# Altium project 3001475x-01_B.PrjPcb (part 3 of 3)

## Sheet 11 - Expansion Connectors, User LEDs.SchDoc: Expansion connectors, User LEDs
size A3; PageSetup: Record=PageOptions|CenterHorizontal=True|CenterVertical=True|PrintScale=0.70|XCorrection=1.00|YCorrection=1.00|PrintKind=0|BorderSize=5000000|LeftOffset=0|BottomOffset=0|Orientation=2|PaperLength=4200|PaperWidth=2970|Scale=100|PaperSource=7|PrintQuality=600|MediaType=1|DitherType=10|PaperKind=A4|PrintScaleMode=1; Author: Daniel Alesanco; SheetNumber: 11; SheetTotal: 13
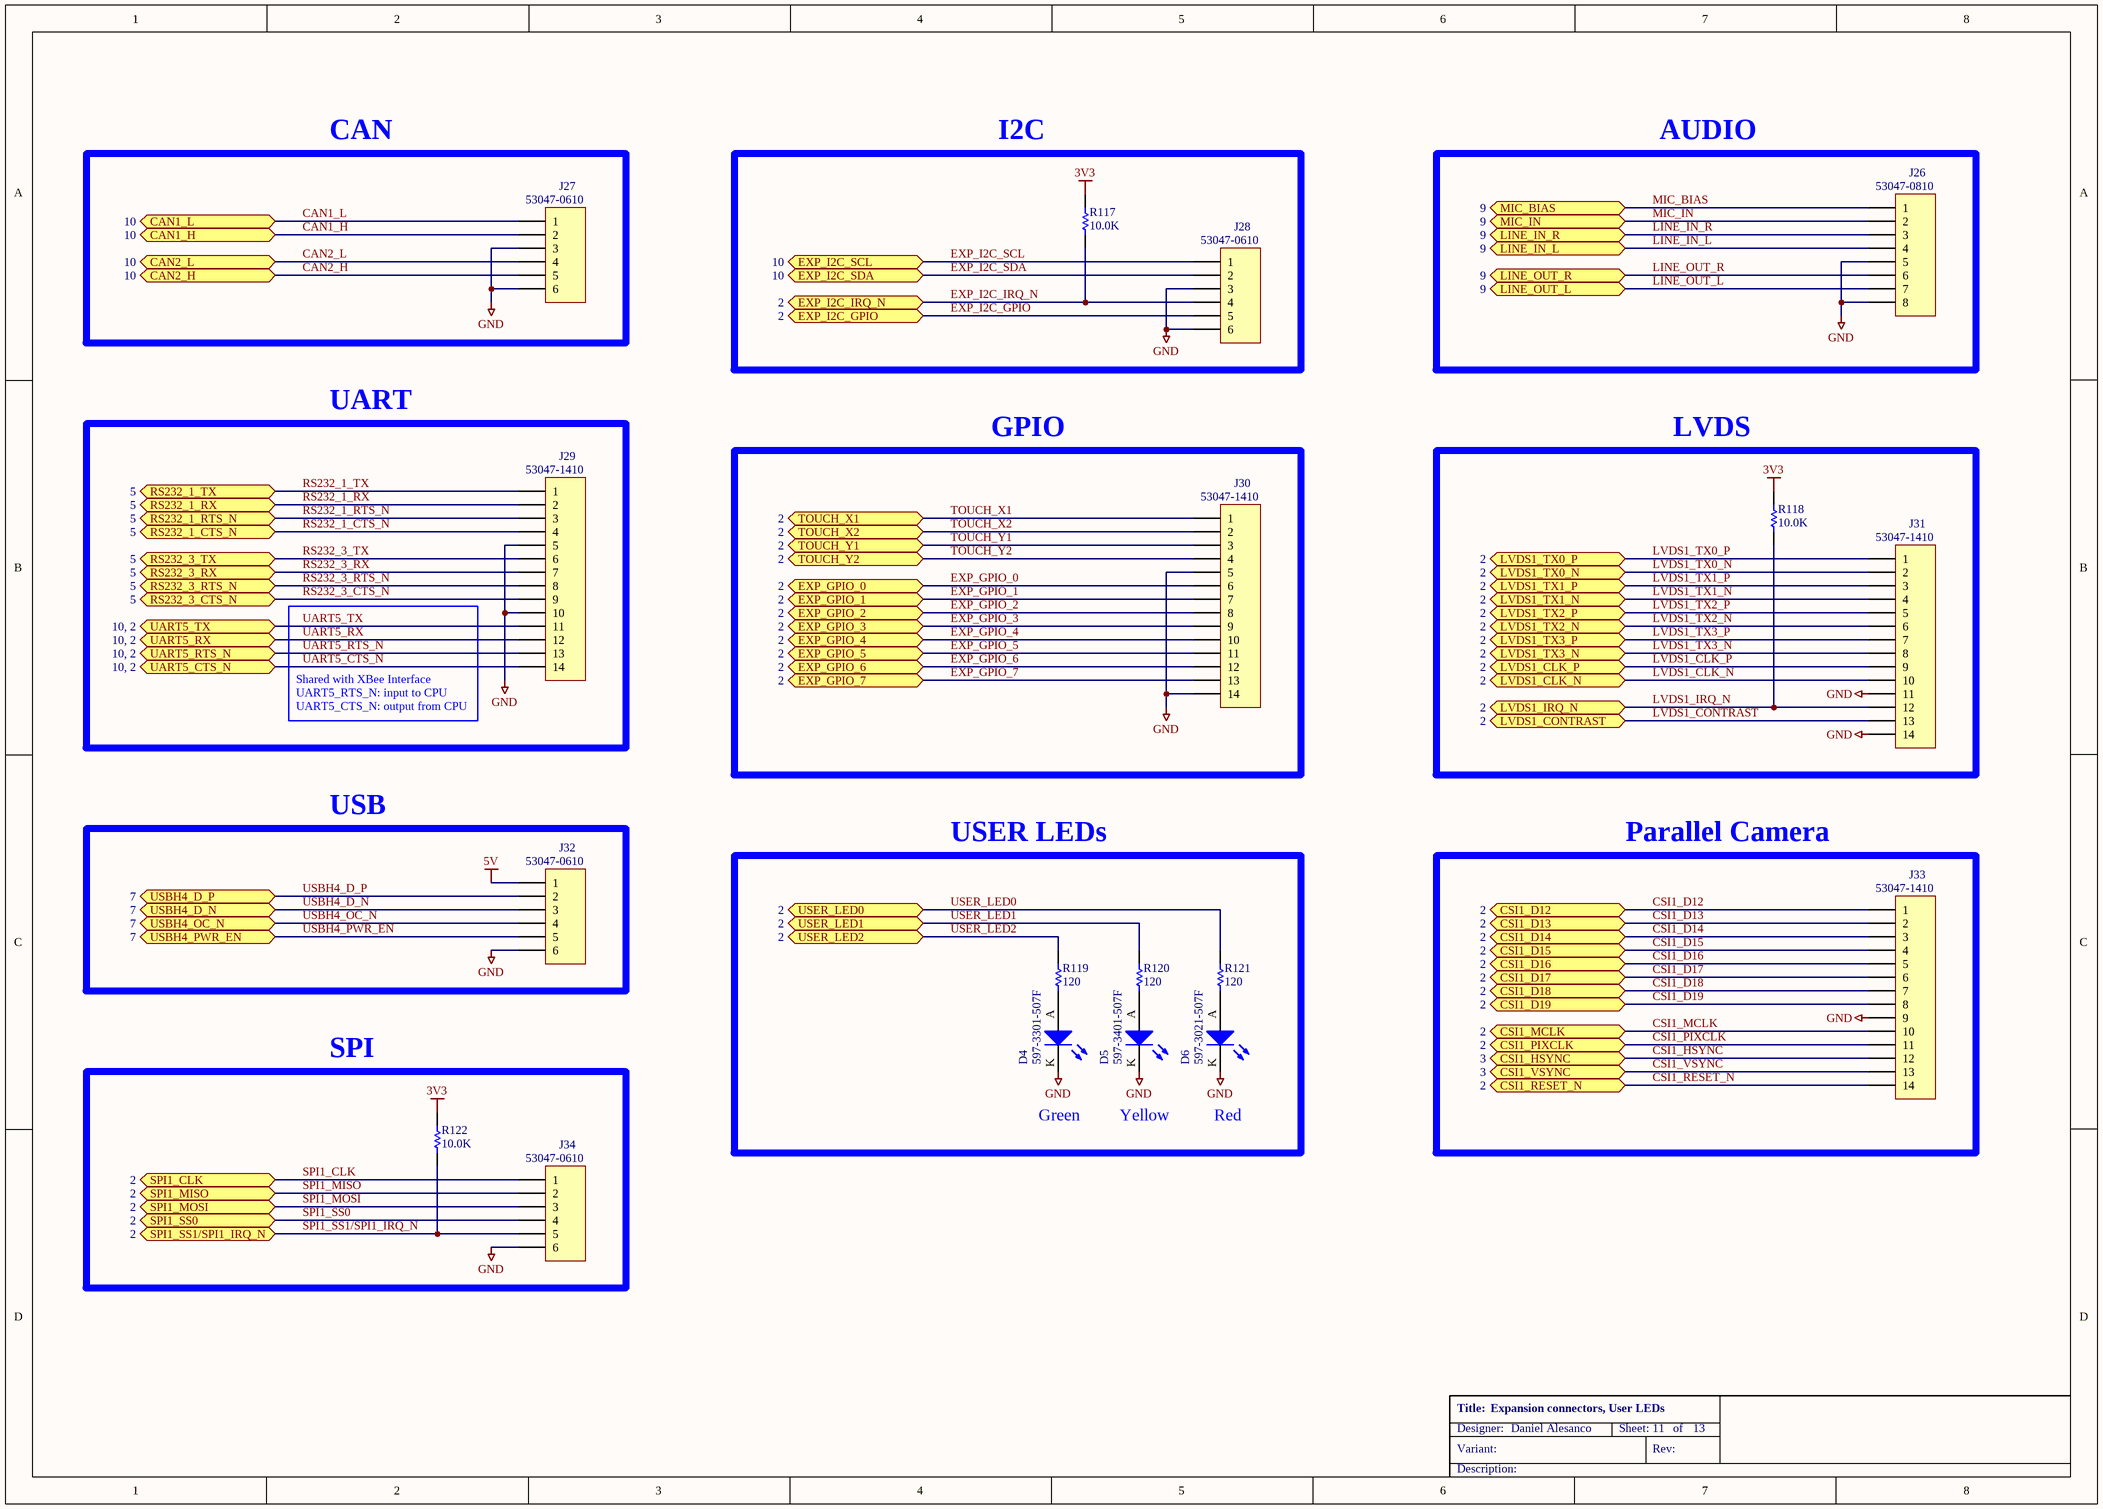
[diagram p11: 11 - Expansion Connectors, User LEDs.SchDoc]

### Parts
D4  597-3301-507F  [LEDM3020X130N]
D5  597-3401-507F  [LEDM3020X130N]
D6  597-3021-507F  [LEDM3020X130N]
J26  Manufacturer_Part_Number: 53047-0810  [MOLEX_53047-0810]  (hidden comment: 1x8P)
J27  Manufacturer_Part_Number: 53047-0610  [MOLEX_53047-0610]  (hidden comment: 1x6P)
J28  Manufacturer_Part_Number: 53047-0610  [MOLEX_53047-0610]  (hidden comment: 1x6P)
J29  Manufacturer_Part_Number: 53047-1410  [MOLEX_53047-1410]  (hidden comment: 1x14P)
J30  Manufacturer_Part_Number: 53047-1410  [MOLEX_53047-1410]  (hidden comment: 1x14P)
J31  Manufacturer_Part_Number: 53047-1410  [MOLEX_53047-1410]  (hidden comment: 1x14P)
J32  Manufacturer_Part_Number: 53047-0610  [MOLEX_53047-0610]  (hidden comment: 1x6P)
J33  Manufacturer_Part_Number: 53047-1410  [MOLEX_53047-1410]  (hidden comment: 1x14P)
J34  Manufacturer_Part_Number: 53047-0610  [MOLEX_53047-0610]  (hidden comment: 1x6P)
R117  10.0K  [RESC1005X40N]
R118  10.0K  [RESC1005X40N]
R119  120  [RESC1005X40N]
R120  120  [RESC1005X40N]
R121  120  [RESC1005X40N]
R122  10.0K  [RESC1005X40N]

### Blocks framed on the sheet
CAN: J27
I2C: J28 R117
AUDIO: J26
UART: J29
GPIO: J30
LVDS: J31 R118
USB: J32
USER LEDs: D4-D6 R119-R121
Parallel Camera: J33
SPI: J34 R122

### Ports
CAN1_H (bidir, see 10), CAN1_L (bidir, see 10), CAN2_H (bidir, see 10), CAN2_L (bidir, see 10), CSI1_D12 (bidir, see 2), CSI1_D13 (bidir, see 2), CSI1_D14 (bidir, see 2), CSI1_D15 (bidir, see 2), CSI1_D16 (bidir, see 2), CSI1_D17 (bidir, see 2), CSI1_D18 (bidir, see 2), CSI1_D19 (bidir, see 2), CSI1_HSYNC (bidir, see 3), CSI1_MCLK (bidir, see 2), CSI1_PIXCLK (bidir, see 2), CSI1_RESET_N (bidir, see 2), CSI1_VSYNC (bidir, see 3), EXP_GPIO_0 (bidir, see 2), EXP_GPIO_1 (bidir, see 2), EXP_GPIO_2 (bidir, see 2), EXP_GPIO_3 (bidir, see 2), EXP_GPIO_4 (bidir, see 2), EXP_GPIO_5 (bidir, see 2), EXP_GPIO_6 (bidir, see 2), EXP_GPIO_7 (bidir, see 2), EXP_I2C_GPIO (bidir, see 2), EXP_I2C_IRQ_N (bidir, see 2), EXP_I2C_SCL (bidir, see 10), EXP_I2C_SDA (bidir, see 10), LINE_IN_L (bidir, see 9), LINE_IN_R (bidir, see 9), LINE_OUT_L (bidir, see 9), LINE_OUT_R (bidir, see 9), LVDS1_CLK_N (bidir, see 2), LVDS1_CLK_P (bidir, see 2), LVDS1_CONTRAST (bidir, see 2), LVDS1_IRQ_N (bidir, see 2), LVDS1_TX0_N (bidir, see 2), LVDS1_TX0_P (bidir, see 2), LVDS1_TX1_N (bidir, see 2), LVDS1_TX1_P (bidir, see 2), LVDS1_TX2_N (bidir, see 2), LVDS1_TX2_P (bidir, see 2), LVDS1_TX3_N (bidir, see 2), LVDS1_TX3_P (bidir, see 2), MIC_BIAS (bidir, see 9), MIC_IN (bidir, see 9), RS232_1_CTS_N (bidir, see 5), RS232_1_RTS_N (bidir, see 5), RS232_1_RX (bidir, see 5), RS232_1_TX (bidir, see 5), RS232_3_CTS_N (bidir, see 5), RS232_3_RTS_N (bidir, see 5), RS232_3_RX (bidir, see 5), RS232_3_TX (bidir, see 5), SPI1_CLK (bidir, see 2), SPI1_MISO (bidir, see 2), SPI1_MOSI (bidir, see 2), SPI1_SS0 (bidir, see 2), SPI1_SS1/SPI1_IRQ_N (bidir, see 2), TOUCH_X1 (bidir, see 2), TOUCH_X2 (bidir, see 2), TOUCH_Y1 (bidir, see 2), TOUCH_Y2 (bidir, see 2), UART5_CTS_N (bidir, see 10, 2), UART5_RTS_N (bidir, see 10, 2), UART5_RX (bidir, see 10, 2), UART5_TX (bidir, see 10, 2), USBH4_D_N (bidir, see 7), USBH4_D_P (bidir, see 7), USBH4_OC_N (bidir, see 7), USBH4_PWR_EN (bidir, see 7), USER_LED0 (bidir, see 2), USER_LED1 (bidir, see 2), USER_LED2 (bidir, see 2)

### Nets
3V3: R117.1 R118.1 R122.1
5V: J32.1
GND: D4.K D5.K D6.K J26.5 J26.8 J27.3 J27.6 J28.3 J28.6 J29.5 J29.10 J30.5 J30.14 J31.11 J31.14 J32.6 J33.9 J34.6
CAN1_H: J27.2 ; port CAN1_H
CAN1_L: J27.1 ; port CAN1_L
CAN2_H: J27.5 ; port CAN2_H
CAN2_L: J27.4 ; port CAN2_L
CSI1_D12: J33.1 ; port CSI1_D12
CSI1_D13: J33.2 ; port CSI1_D13
CSI1_D14: J33.3 ; port CSI1_D14
CSI1_D15: J33.4 ; port CSI1_D15
CSI1_D16: J33.5 ; port CSI1_D16
CSI1_D17: J33.6 ; port CSI1_D17
CSI1_D18: J33.7 ; port CSI1_D18
CSI1_D19: J33.8 ; port CSI1_D19
CSI1_HSYNC: J33.12 ; port CSI1_HSYNC
CSI1_MCLK: J33.10 ; port CSI1_MCLK
CSI1_PIXCLK: J33.11 ; port CSI1_PIXCLK
CSI1_RESET_N: J33.14 ; port CSI1_RESET_N
CSI1_VSYNC: J33.13 ; port CSI1_VSYNC
EXP_GPIO_0: J30.6 ; port EXP_GPIO_0
EXP_GPIO_1: J30.7 ; port EXP_GPIO_1
EXP_GPIO_2: J30.8 ; port EXP_GPIO_2
EXP_GPIO_3: J30.9 ; port EXP_GPIO_3
EXP_GPIO_4: J30.10 ; port EXP_GPIO_4
EXP_GPIO_5: J30.11 ; port EXP_GPIO_5
EXP_GPIO_6: J30.12 ; port EXP_GPIO_6
EXP_GPIO_7: J30.13 ; port EXP_GPIO_7
EXP_I2C_GPIO: J28.5 ; port EXP_I2C_GPIO
EXP_I2C_IRQ_N: J28.4 R117.2 ; port EXP_I2C_IRQ_N
EXP_I2C_SCL: J28.1 ; port EXP_I2C_SCL
EXP_I2C_SDA: J28.2 ; port EXP_I2C_SDA
LINE_IN_L: J26.4 ; port LINE_IN_L
LINE_IN_R: J26.3 ; port LINE_IN_R
LINE_OUT_L: J26.7 ; port LINE_OUT_L
LINE_OUT_R: J26.6 ; port LINE_OUT_R
LVDS1_CLK_N: J31.10 ; port LVDS1_CLK_N
LVDS1_CLK_P: J31.9 ; port LVDS1_CLK_P
LVDS1_CONTRAST: J31.13 ; port LVDS1_CONTRAST
LVDS1_IRQ_N: J31.12 R118.2 ; port LVDS1_IRQ_N
LVDS1_TX0_N: J31.2 ; port LVDS1_TX0_N
LVDS1_TX0_P: J31.1 ; port LVDS1_TX0_P
LVDS1_TX1_N: J31.4 ; port LVDS1_TX1_N
LVDS1_TX1_P: J31.3 ; port LVDS1_TX1_P
LVDS1_TX2_N: J31.6 ; port LVDS1_TX2_N
LVDS1_TX2_P: J31.5 ; port LVDS1_TX2_P
LVDS1_TX3_N: J31.8 ; port LVDS1_TX3_N
LVDS1_TX3_P: J31.7 ; port LVDS1_TX3_P
MIC_BIAS: J26.1 ; port MIC_BIAS
MIC_IN: J26.2 ; port MIC_IN
RS232_1_CTS_N: J29.4 ; port RS232_1_CTS_N
RS232_1_RTS_N: J29.3 ; port RS232_1_RTS_N
RS232_1_RX: J29.2 ; port RS232_1_RX
RS232_1_TX: J29.1 ; port RS232_1_TX
RS232_3_CTS_N: J29.9 ; port RS232_3_CTS_N
RS232_3_RTS_N: J29.8 ; port RS232_3_RTS_N
RS232_3_RX: J29.7 ; port RS232_3_RX
RS232_3_TX: J29.6 ; port RS232_3_TX
SPI1_CLK: J34.1 ; port SPI1_CLK
SPI1_MISO: J34.2 ; port SPI1_MISO
SPI1_MOSI: J34.3 ; port SPI1_MOSI
SPI1_SS0: J34.4 ; port SPI1_SS0
SPI1_SS1/SPI1_IRQ_N: J34.5 R122.2 ; port SPI1_SS1/SPI1_IRQ_N
TOUCH_X1: J30.1 ; port TOUCH_X1
TOUCH_X2: J30.2 ; port TOUCH_X2
TOUCH_Y1: J30.3 ; port TOUCH_Y1
TOUCH_Y2: J30.4 ; port TOUCH_Y2
UART5_CTS_N: J29.14 ; port UART5_CTS_N
UART5_RTS_N: J29.13 ; port UART5_RTS_N
UART5_RX: J29.12 ; port UART5_RX
UART5_TX: J29.11 ; port UART5_TX
USBH4_D_N: J32.3 ; port USBH4_D_N
USBH4_D_P: J32.2 ; port USBH4_D_P
USBH4_OC_N: J32.4 ; port USBH4_OC_N
USBH4_PWR_EN: J32.5 ; port USBH4_PWR_EN
USER_LED0: R121.2 ; port USER_LED0
USER_LED1: R120.2 ; port USER_LED1
USER_LED2: R119.2 ; port USER_LED2
NetD4_A: D4.A R119.1
NetD5_A: D5.A R120.1
NetD6_A: D6.A R121.1

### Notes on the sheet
- Shared with XBee Interface
- UART5_RTS_N: input to CPU
- UART5_CTS_N: output from CPU
- Green
- Yellow
- Red

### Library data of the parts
D4 = 1001189: LED GREEN 573NM 1208 SMD; Manufacturer: Dialight; Digi_PN: 17050183; Component_Life_Cycle_State: Reviewed; Area: 6; Project: CCWMX6_SBC board
D5 = 1001188: LED YELLOW 588NM 1208 SMD; Manufacturer: Dialight; Digi_PN: 17050387; Component_Life_Cycle_State: Reviewed; Area: 6; Project: CCWMX6_SBC board
D6 = 1001190: LED RED 653NM 20MA 1208 SMD; Manufacturer: Dialight; Digi_PN: 17050184; Component_Life_Cycle_State: Reviewed; Area: 6; Project: CCWMX6_SBC board
J26 = 1001139: CONN HEADER 8POS 1.25MM VERT TIN; Part_Type: Connector; Manufacturer: Molex; Digi_PN: 18050346; Component_Life_Cycle_State: Reviewed; Area: 37.6; Project: CCWMX6_SBC board
J27 J28 J32 J34 = 1001138: CONN HEADER 6POS 1.25MM VERT TIN; Part_Type: Connector; Manufacturer: Molex; Digi_PN: 18050345; Component_Life_Cycle_State: Reviewed; Area: 29.6; Project: CCWMX6_SBC board
J29-J31 J33 = 1001140: CONN HEADER 14POS 1.25MM STR TIN; Part_Type: Connector; Manufacturer: Molex; Digi_PN: 18050347; Component_Life_Cycle_State: Reviewed; Area: 61.6; Project: CCWMX6_SBC board
R117 R118 R122 = 1000537: RES 10.0K OHM 1/10W 1% 0402 SMD; Part_Type: Resistor; Manufacturer: Panasonic - ECG; Manufacturer_Part_Number: ERJ-2RKF1002X; Component_Life_Cycle_State: CAD Reviewed; Area: 0.95; Project: KITT; Power_WV_SRF: 100; Digi_PN: 13050644
R119-R121 = 1001158: RES 120 OHM 1/16W 1% 0402 SMD; Part_Type: Resistor; Manufacturer: Yageo; Manufacturer_Part_Number: RC0402FR-07120RL; Digi_PN: 13050832; Component_Life_Cycle_State: Reviewed; Area: 0.95; Project: CCWMX6_SBC board

## Sheet 12 - GPIO Table, System Power rails.SchDoc: GPIO Table, System Power rails
size A3; PageSetup: Record=PageOptions|CenterHorizontal=True|CenterVertical=True|PrintScale=0.70|XCorrection=1.00|YCorrection=1.00|PrintKind=0|BorderSize=5000000|LeftOffset=0|BottomOffset=0|Orientation=2|PaperLength=4200|PaperWidth=2970|Scale=100|PaperSource=7|PrintQuality=600|MediaType=1|DitherType=10|PaperKind=A4|PrintScaleMode=1; Author: Daniel Alesanco; SheetNumber: 12; SheetTotal: 13
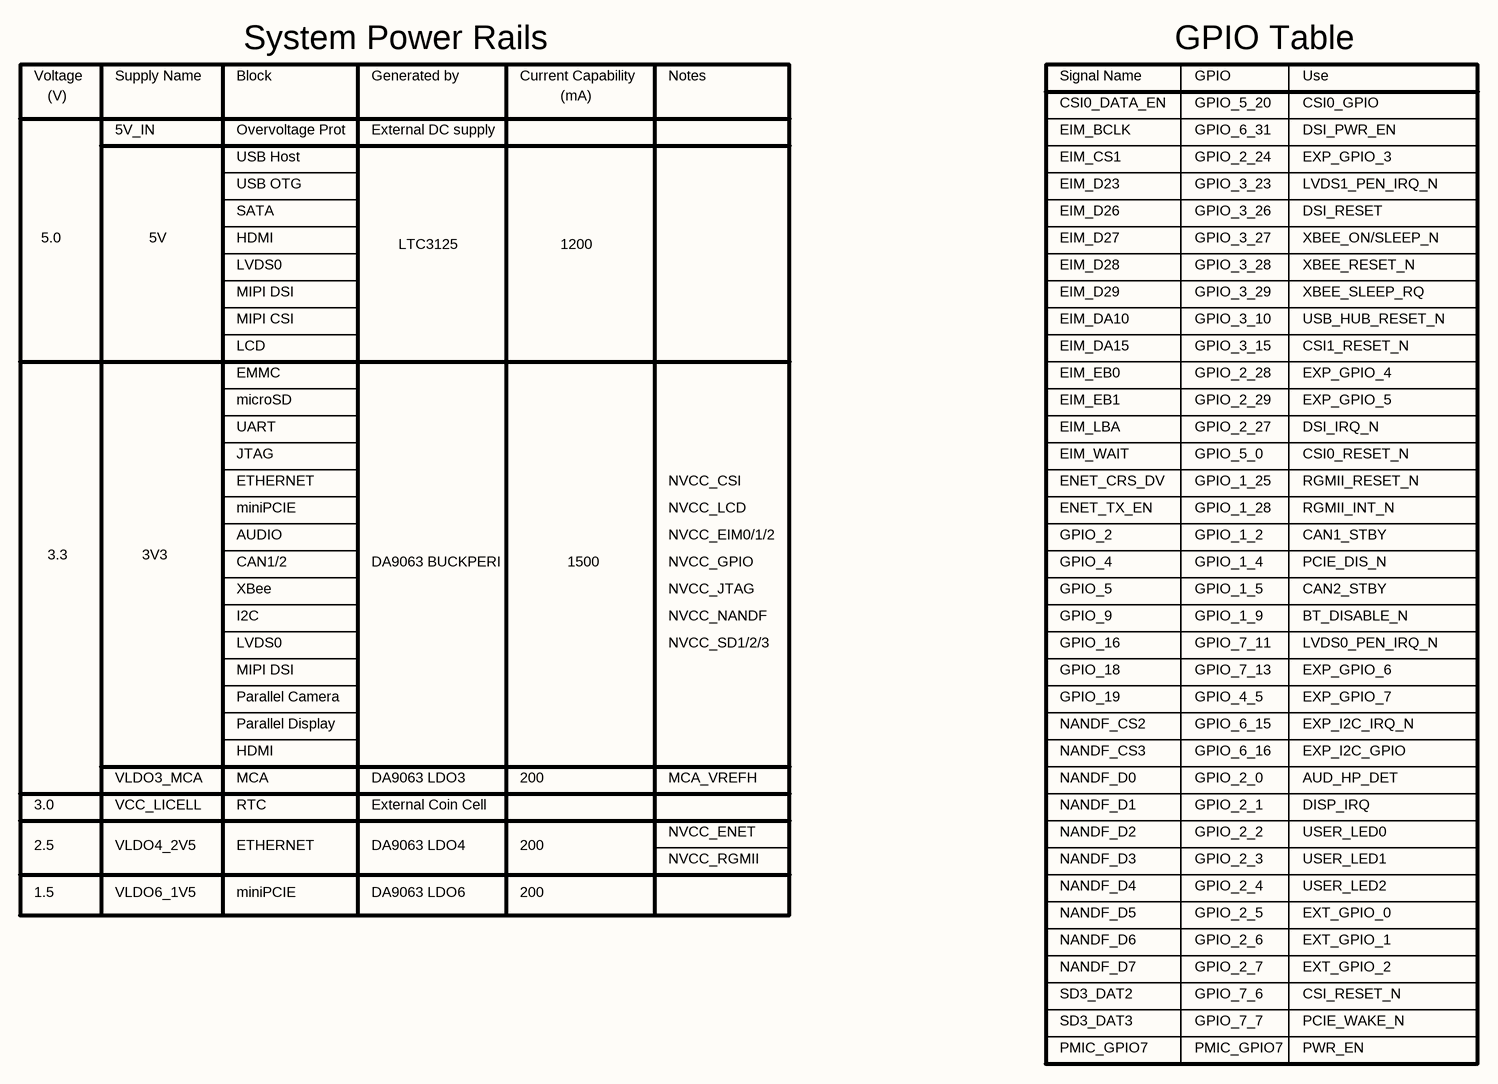
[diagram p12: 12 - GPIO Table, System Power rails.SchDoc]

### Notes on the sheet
- Voltage
- (V)
- Supply Name
- Block
- System Power Rails
- Generated by
- Current Capability
- (mA)
- Notes
- Signal Name
- CSI0_DATA_EN
- GPIO Table
- GPIO
- GPIO_5_20
- Use
- CSI0_GPIO
- 5V_IN
- Overvoltage Prot
- USB Host
- External DC supply
- EIM_BCLK
- EIM_CS1
- GPIO_6_31
- GPIO_2_24
- DSI_PWR_EN
- EXP_GPIO_3
- 5.0
- 5V
- USB OTG
- SATA
- HDMI
- LTC3125
- 1200
- EIM_D23
- EIM_D26
- EIM_D27
- GPIO_3_23
- GPIO_3_26
- GPIO_3_27
- LVDS1_PEN_IRQ_N
- DSI_RESET
- XBEE_ON/SLEEP_N
- LVDS0
- MIPI DSI
- EIM_D28
- EIM_D29
- GPIO_3_28
- GPIO_3_29
- XBEE_RESET_N
- XBEE_SLEEP_RQ
- MIPI CSI
- LCD
- EMMC
- EIM_DA10
- EIM_DA15
- EIM_EB0
- GPIO_3_10
- GPIO_3_15
- GPIO_2_28
- USB_HUB_RESET_N
- CSI1_RESET_N
- EXP_GPIO_4
- microSD
- UART
- EIM_EB1
- EIM_LBA
- GPIO_2_29
- GPIO_2_27
- EXP_GPIO_5
- DSI_IRQ_N
- JTAG
- ETHERNET
- miniPCIE
- NVCC_CSI
- NVCC_LCD
- EIM_WAIT
- ENET_CRS_DV
- ENET_TX_EN
- GPIO_5_0
- GPIO_1_25
- GPIO_1_28
- CSI0_RESET_N
- RGMII_RESET_N
- RGMII_INT_N
- 3.3
- 3V3
- AUDIO
- CAN1/2
- DA9063 BUCKPERI
- 1500
- NVCC_EIM0/1/2
- NVCC_GPIO
- GPIO_2
- GPIO_4
- GPIO_1_2
- GPIO_1_4
- CAN1_STBY
- PCIE_DIS_N
- XBee
- I2C
- NVCC_JTAG
- NVCC_NANDF
- NVCC_SD1/2/3
- GPIO_16
- GPIO_5
- GPIO_9
- GPIO_1_5
- GPIO_1_9
- GPIO_7_11
- CAN2_STBY
- BT_DISABLE_N
- LVDS0_PEN_IRQ_N
- Parallel Camera
- GPIO_18
- GPIO_19
- GPIO_7_13
- GPIO_4_5
- EXP_GPIO_6
- EXP_GPIO_7
- VLDO3_MCA
- Parallel Display
- MCA
- DA9063 LDO3
- 200
- MCA_VREFH
- NANDF_D0
- NANDF_CS2
- NANDF_CS3
- GPIO_2_0
- GPIO_6_15
- GPIO_6_16
- AUD_HP_DET
- EXP_I2C_IRQ_N
- EXP_I2C_GPIO
- 3.0
- 2.5
- VCC_LICELL
- VLDO4_2V5
- RTC
- External Coin Cell
- DA9063 LDO4
- NVCC_ENET
- NANDF_D1
- NANDF_D2
- GPIO_2_1
- GPIO_2_2
- DISP_IRQ
- USER_LED0
- 1.5
- VLDO6_1V5
- DA9063 LDO6
- NVCC_RGMII
- NANDF_D3
- NANDF_D4
- NANDF_D5
- GPIO_2_3
- GPIO_2_4
- GPIO_2_5
- USER_LED1
- USER_LED2
- EXT_GPIO_0
- NANDF_D6
- NANDF_D7
- GPIO_2_6
- GPIO_2_7
- EXT_GPIO_1
- EXT_GPIO_2
- SD3_DAT2
- SD3_DAT3
- PMIC_GPIO7
- GPIO_7_6
- GPIO_7_7
- CSI_RESET_N
- PCIE_WAKE_N
- PWR_EN

## Sheet 13 - History, Mechanicals.SchDoc: History
size A3; PageSetup: Record=PageOptions|CenterHorizontal=True|CenterVertical=True|PrintScale=0.70|XCorrection=1.00|YCorrection=1.00|PrintKind=0|BorderSize=5000000|LeftOffset=0|BottomOffset=0|Orientation=2|PaperLength=4200|PaperWidth=2970|Scale=100|PaperSource=7|PrintQuality=600|MediaType=1|DitherType=10|PaperKind=A4|PrintScaleMode=1; Author: Daniel Alesanco; SheetNumber: 13; SheetTotal: 13
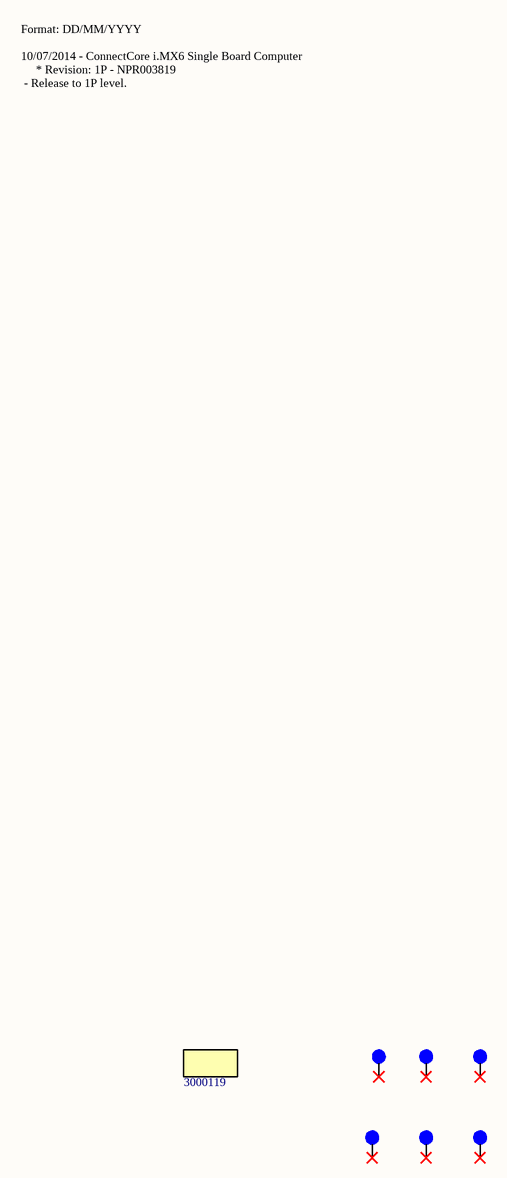
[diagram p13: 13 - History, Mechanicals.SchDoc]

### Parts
FIDUCIAL1  40mil FID  [fiducial_40mil_round]  (value not drawn)
FIDUCIAL2  40mil FID  [fiducial_40mil_round]  (value not drawn)
FIDUCIAL3  40mil FID  [fiducial_40mil_round]  (value not drawn)
FIDUCIAL4  40mil FID  [fiducial_40mil_round]  (value not drawn)
FIDUCIAL5  40mil FID  [fiducial_40mil_round]  (value not drawn)
FIDUCIAL6  40mil FID  [fiducial_40mil_round]  (value not drawn)
PCB1  3000119

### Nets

Not connected (* = marked no-connect by the designer): FIDUCIAL1 1(Fid_1)*; FIDUCIAL2 1(Fid_1)*; FIDUCIAL3 1(Fid_1)*; FIDUCIAL4 1(Fid_1)*; FIDUCIAL5 1(Fid_1)*; FIDUCIAL6 1(Fid_1)*

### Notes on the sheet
- Format: DD/MM/YYYY
  10/07/2014 - ConnectCore i.MX6 Single Board Computer
  * Revision: 1P - NPR003819
  - Release to 1P level.

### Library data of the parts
FIDUCIAL1-FIDUCIAL6 = CAD0023: 40 Mil Round Fiducial; Part_Type: Mechanical; Component_Life_Cycle_State: Reviewed; Area: 1; Project: SDR Prototype RF Board
PCB1 = 3000119: PCB CCWM6_SBC_v0.1; Digi_PN: 30014752-01; Component_Life_Cycle_State: Created; Project: CCWMX6_SBC board

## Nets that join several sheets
3V3: 02 - CCIMX6 Module (9 pins), 03 - Power, Battery charger, boot (13 pins), 04 - SATA, microSD (8 pins), 05 - JTAG, SWD, Console, UART (12 pins), 06 - Gigabit Ethernet, Mini PCIe, microSIM (15 pins), 07 - USB OTG, USB HUB, USB Host (8 pins), 08 - Displays, HDMI, Cameras (14 pins), 09 - Audio (5 pins), 10 - CAN, I2C, XBee (7 pins), 11 - Expansion Connectors, User LEDs (R117.1 R118.1 R122.1)
5V: 02 - CCIMX6 Module (U1.F16), 03 - Power, Battery charger, boot (R21.2), 04 - SATA, microSD (J6.1), 07 - USB OTG, USB HUB, USB Host (C62.2 C65.1 U12.7 U14.7), 08 - Displays, HDMI, Cameras (12 pins), 11 - Expansion Connectors, User LEDs (J32.1)
GND: 02 - CCIMX6 Module (60 pins), 03 - Power, Battery charger, boot (36 pins), 04 - SATA, microSD (9 pins), 05 - JTAG, SWD, Console, UART (15 pins), 06 - Gigabit Ethernet, Mini PCIe, microSIM (68 pins), 07 - USB OTG, USB HUB, USB Host (38 pins), 08 - Displays, HDMI, Cameras (47 pins), 09 - Audio (10 pins), 10 - CAN, I2C, XBee (7 pins), 11 - Expansion Connectors, User LEDs (18 pins)
SHLD: 04 - SATA, microSD (J7.11 J7.12), 06 - Gigabit Ethernet, Mini PCIe, microSIM (C33.1 J13.SHLD1 J13.SHLD2 R46.2), 07 - USB OTG, USB HUB, USB Host (8 pins), 08 - Displays, HDMI, Cameras (P1.M1 P1.M2 P1.M3 P1.M4)
VCC_LICELL: 02 - CCIMX6 Module (U1.N3), 03 - Power, Battery charger, boot (R8.2)
VLDO3_MCA: 02 - CCIMX6 Module (U1.AC10 U1.M22), 05 - JTAG, SWD, Console, UART (J11.1)
VLDO4_2V5: 02 - CCIMX6 Module (U1.AD10 U1.R5 U1.V3), 06 - Gigabit Ethernet, Mini PCIe, microSIM (10 pins)
VLDO6_1V5: 02 - CCIMX6 Module (U1.AA10), 06 - Gigabit Ethernet, Mini PCIe, microSIM (5 pins)
VSYS: 02 - CCIMX6 Module (U1.V11 U1.W11 U1.W12), 03 - Power, Battery charger, boot (14 pins)
AUD_CLK: 02 - CCIMX6 Module (R1.2), 09 - Audio (U17.21)
AUD_HP_DET: 02 - CCIMX6 Module (U1.J24), 09 - Audio (D9.2 J22.5 R93.1)
AUD_I2C_SCL: 09 - Audio (U17.29), 10 - CAN, I2C, XBee (R114.2)
AUD_I2C_SDA: 09 - Audio (U17.27), 10 - CAN, I2C, XBee (R115.2)
AUD_RXD: 02 - CCIMX6 Module (U1.M5), 09 - Audio (U17.25)
AUD_TXC: 02 - CCIMX6 Module (U1.B7), 09 - Audio (U17.24)
AUD_TXD: 02 - CCIMX6 Module (U1.C7), 09 - Audio (U17.26)
AUD_TXFS: 02 - CCIMX6 Module (U1.C5), 09 - Audio (U17.23)
BOOT_CFG_1_4: 02 - CCIMX6 Module (U1.W24), 03 - Power, Battery charger, boot (R18.1)
BOOT_CFG_1_5: 02 - CCIMX6 Module (U1.AA19), 03 - Power, Battery charger, boot (J5.1 R10.1 U4.1)
BOOT_CFG_1_6: 02 - CCIMX6 Module (U1.U23), 03 - Power, Battery charger, boot (J4.1 R9.1 U2.1)
BOOT_CFG_1_7: 02 - CCIMX6 Module (U1.Y21), 03 - Power, Battery charger, boot (R19.1)
BOOT_CFG_2_5: 02 - CCIMX6 Module (U1.V20), 03 - Power, Battery charger, boot (R16.1)
BOOT_CFG_2_6: 02 - CCIMX6 Module (U1.W21), 03 - Power, Battery charger, boot (R17.1)
BOOT_MODE0: 02 - CCIMX6 Module (U1.E17), 03 - Power, Battery charger, boot (R24.1 R28.2)
BOOT_MODE1: 02 - CCIMX6 Module (U1.F15), 03 - Power, Battery charger, boot (R25.1 R29.2)
CAN1_H: 10 - CAN, I2C, XBee (R104.2 U18.7), 11 - Expansion Connectors, User LEDs (J27.2)
CAN1_L: 10 - CAN, I2C, XBee (R104.1 U18.6), 11 - Expansion Connectors, User LEDs (J27.1)
CAN1_RXD: 02 - CCIMX6 Module (U1.F3), 10 - CAN, I2C, XBee (U18.4)
CAN1_STBY: 02 - CCIMX6 Module (U1.G3), 10 - CAN, I2C, XBee (U18.8)
CAN1_TXD: 02 - CCIMX6 Module (U1.P3), 10 - CAN, I2C, XBee (U18.1)
CAN2_H: 10 - CAN, I2C, XBee (R116.2 U19.7), 11 - Expansion Connectors, User LEDs (J27.5)
CAN2_L: 10 - CAN, I2C, XBee (R116.1 U19.6), 11 - Expansion Connectors, User LEDs (J27.4)
CAN2_RXD: 02 - CCIMX6 Module (U1.D21), 10 - CAN, I2C, XBee (U19.4)
CAN2_STBY: 02 - CCIMX6 Module (U1.R3), 10 - CAN, I2C, XBee (U19.8)
CAN2_TXD: 02 - CCIMX6 Module (U1.F20), 10 - CAN, I2C, XBee (U19.1)
CLK1_N: 02 - CCIMX6 Module (U1.B18), 06 - Gigabit Ethernet, Mini PCIe, microSIM (C31.1)
CLK1_P: 02 - CCIMX6 Module (U1.A18), 06 - Gigabit Ethernet, Mini PCIe, microSIM (C32.1)
CSI0_DAT12: 02 - CCIMX6 Module (U1.L5), 08 - Displays, HDMI, Cameras (J17.2)
CSI0_DAT13: 02 - CCIMX6 Module (U1.C6), 08 - Displays, HDMI, Cameras (J17.3)
CSI0_DAT14: 02 - CCIMX6 Module (U1.B6), 08 - Displays, HDMI, Cameras (J17.4)
CSI0_DAT15: 02 - CCIMX6 Module (U1.E6), 08 - Displays, HDMI, Cameras (J17.5)
CSI0_DAT16: 02 - CCIMX6 Module (U1.H6), 08 - Displays, HDMI, Cameras (J17.6)
CSI0_DAT17: 02 - CCIMX6 Module (U1.A7), 08 - Displays, HDMI, Cameras (J17.7)
CSI0_DAT18: 02 - CCIMX6 Module (U1.F6), 08 - Displays, HDMI, Cameras (J17.8)
CSI0_DAT19: 02 - CCIMX6 Module (U1.G6), 08 - Displays, HDMI, Cameras (J17.9)
CSI0_GPIO: 02 - CCIMX6 Module (U1.E5), 08 - Displays, HDMI, Cameras (J17.15)
CSI0_HSYNC: 02 - CCIMX6 Module (U1.A5), 08 - Displays, HDMI, Cameras (J17.13)
CSI0_I2C_SCL: 08 - Displays, HDMI, Cameras (J17.18), 10 - CAN, I2C, XBee (R108.2)
CSI0_I2C_SDA: 08 - Displays, HDMI, Cameras (J17.19), 10 - CAN, I2C, XBee (R111.2)
CSI0_MCLK: 02 - CCIMX6 Module (R3.2), 08 - Displays, HDMI, Cameras (J17.11)
CSI0_PIXCLK: 02 - CCIMX6 Module (U1.G5), 08 - Displays, HDMI, Cameras (J17.12)
CSI0_RESET_N: 02 - CCIMX6 Module (U1.AA13), 08 - Displays, HDMI, Cameras (J17.16)
CSI0_VSYNC: 02 - CCIMX6 Module (U1.J5), 08 - Displays, HDMI, Cameras (J17.14)
CSI1_D12: 02 - CCIMX6 Module (U1.AC17), 11 - Expansion Connectors, User LEDs (J33.1)
CSI1_D13: 02 - CCIMX6 Module (U1.AB15), 11 - Expansion Connectors, User LEDs (J33.2)
CSI1_D14: 02 - CCIMX6 Module (U1.AD16), 11 - Expansion Connectors, User LEDs (J33.3)
CSI1_D15: 02 - CCIMX6 Module (U1.AB16), 11 - Expansion Connectors, User LEDs (J33.4)
CSI1_D16: 02 - CCIMX6 Module (U1.AC16), 11 - Expansion Connectors, User LEDs (J33.5)
CSI1_D17: 02 - CCIMX6 Module (U1.AC19), 11 - Expansion Connectors, User LEDs (J33.6)
CSI1_D18: 02 - CCIMX6 Module (U1.AA14), 11 - Expansion Connectors, User LEDs (J33.7)
CSI1_D19: 02 - CCIMX6 Module (U1.AD17), 11 - Expansion Connectors, User LEDs (J33.8)
CSI1_HSYNC: 03 - Power, Battery charger, boot (U2.3), 11 - Expansion Connectors, User LEDs (J33.12)
CSI1_HSYNC/BTCFG2_3: 02 - CCIMX6 Module (U1.V18), 03 - Power, Battery charger, boot (U2.4)
CSI1_MCLK: 02 - CCIMX6 Module (R2.2), 11 - Expansion Connectors, User LEDs (J33.10)
CSI1_PIXCLK: 02 - CCIMX6 Module (U1.AD15), 11 - Expansion Connectors, User LEDs (J33.11)
CSI1_RESET_N: 02 - CCIMX6 Module (U1.Y20), 11 - Expansion Connectors, User LEDs (J33.14)
CSI1_VSYNC: 03 - Power, Battery charger, boot (U4.3), 11 - Expansion Connectors, User LEDs (J33.13)
CSI1_VSYNC/BTCFG2_4: 02 - CCIMX6 Module (U1.V22), 03 - Power, Battery charger, boot (U4.4)
CSI_CLK0_N: 02 - CCIMX6 Module (U1.B11), 08 - Displays, HDMI, Cameras (J20.15)
CSI_CLK0_P: 02 - CCIMX6 Module (U1.A11), 08 - Displays, HDMI, Cameras (J20.14)
CSI_D0_N: 02 - CCIMX6 Module (U1.G12), 08 - Displays, HDMI, Cameras (J20.12)
CSI_D0_P: 02 - CCIMX6 Module (U1.G11), 08 - Displays, HDMI, Cameras (J20.11)
CSI_D1_N: 02 - CCIMX6 Module (U1.A13), 08 - Displays, HDMI, Cameras (J20.18)
CSI_D1_P: 02 - CCIMX6 Module (U1.B13), 08 - Displays, HDMI, Cameras (J20.17)
CSI_D2_N: 02 - CCIMX6 Module (U1.B12), 08 - Displays, HDMI, Cameras (R82.1)
CSI_D2_P: 02 - CCIMX6 Module (U1.C12), 08 - Displays, HDMI, Cameras (R81.1)
CSI_D3_N: 02 - CCIMX6 Module (U1.E11), 08 - Displays, HDMI, Cameras (R80.1)
CSI_D3_P: 02 - CCIMX6 Module (U1.D11), 08 - Displays, HDMI, Cameras (R79.1)
CSI_I2C_SCL: 08 - Displays, HDMI, Cameras (J20.2), 10 - CAN, I2C, XBee (R112.2)
CSI_I2C_SDA: 08 - Displays, HDMI, Cameras (J20.3), 10 - CAN, I2C, XBee (R113.2)
CSI_RESET_N: 02 - CCIMX6 Module (U1.E24), 08 - Displays, HDMI, Cameras (J20.4)
DISP0_CLK: 02 - CCIMX6 Module (U1.V9), 08 - Displays, HDMI, Cameras (J21.27)
DISP0_CONTRAST: 02 - CCIMX6 Module (U1.AD8), 08 - Displays, HDMI, Cameras (J21.32)
DISP0_DAT0: 02 - CCIMX6 Module (U1.AC8), 08 - Displays, HDMI, Cameras (J21.2)
DISP0_DAT1: 02 - CCIMX6 Module (U1.AC9), 08 - Displays, HDMI, Cameras (J21.3)
DISP0_DAT2: 02 - CCIMX6 Module (U1.AD9), 08 - Displays, HDMI, Cameras (J21.4)
DISP0_DAT3: 02 - CCIMX6 Module (U1.AB8), 08 - Displays, HDMI, Cameras (J21.5)
DISP0_DAT4: 02 - CCIMX6 Module (U1.AA9), 08 - Displays, HDMI, Cameras (J21.6)
DISP0_DAT5: 02 - CCIMX6 Module (U1.AD7), 08 - Displays, HDMI, Cameras (J21.7)
DISP0_DAT6: 02 - CCIMX6 Module (U1.AB7), 08 - Displays, HDMI, Cameras (J21.8)
DISP0_DAT7: 02 - CCIMX6 Module (U1.AC7), 08 - Displays, HDMI, Cameras (J21.9)
DISP0_DAT8: 02 - CCIMX6 Module (U1.AA8), 08 - Displays, HDMI, Cameras (J21.10)
DISP0_DAT9: 02 - CCIMX6 Module (U1.AB6), 08 - Displays, HDMI, Cameras (J21.11)
DISP0_DAT10: 02 - CCIMX6 Module (U1.Y8), 08 - Displays, HDMI, Cameras (J21.12)
DISP0_DAT11: 02 - CCIMX6 Module (U1.Y7), 08 - Displays, HDMI, Cameras (J21.13)
DISP0_DAT12: 02 - CCIMX6 Module (U1.AA7), 08 - Displays, HDMI, Cameras (J21.14)
DISP0_DAT13: 02 - CCIMX6 Module (U1.W8), 08 - Displays, HDMI, Cameras (J21.15)
DISP0_DAT14: 02 - CCIMX6 Module (U1.AC6), 08 - Displays, HDMI, Cameras (J21.16)
DISP0_DAT15: 02 - CCIMX6 Module (U1.W7), 08 - Displays, HDMI, Cameras (J21.17)
DISP0_DAT16: 02 - CCIMX6 Module (U1.V6), 08 - Displays, HDMI, Cameras (J21.18)
DISP0_DAT17: 02 - CCIMX6 Module (U1.AB5), 08 - Displays, HDMI, Cameras (J21.19)
DISP0_DAT18: 02 - CCIMX6 Module (U1.AD6), 08 - Displays, HDMI, Cameras (J21.20)
DISP0_DAT19: 02 - CCIMX6 Module (U1.Y6), 08 - Displays, HDMI, Cameras (J21.21)
DISP0_DAT20: 02 - CCIMX6 Module (U1.W6), 08 - Displays, HDMI, Cameras (J21.22)
DISP0_DAT21: 02 - CCIMX6 Module (U1.U6), 08 - Displays, HDMI, Cameras (J21.23)
DISP0_DAT22: 02 - CCIMX6 Module (U1.V7), 08 - Displays, HDMI, Cameras (J21.24)
DISP0_DAT23: 02 - CCIMX6 Module (U1.AA6), 08 - Displays, HDMI, Cameras (J21.25)
DISP0_DRDY: 02 - CCIMX6 Module (U1.V10), 08 - Displays, HDMI, Cameras (J21.31)
DISP0_HSYNC: 02 - CCIMX6 Module (U1.W10), 08 - Displays, HDMI, Cameras (J21.29)
DISP0_I2C_SCL: 08 - Displays, HDMI, Cameras (J21.33), 10 - CAN, I2C, XBee (R103.2)
DISP0_I2C_SDA: 08 - Displays, HDMI, Cameras (J21.34), 10 - CAN, I2C, XBee (R105.2)
DISP0_IRQ_N: 02 - CCIMX6 Module (U1.H22), 08 - Displays, HDMI, Cameras (J21.35 R78.2)
DISP0_VSYNC: 02 - CCIMX6 Module (U1.V8), 08 - Displays, HDMI, Cameras (J21.30)
DSI_CLK0_N: 02 - CCIMX6 Module (U1.E10), 08 - Displays, HDMI, Cameras (J18.7)
DSI_CLK0_P: 02 - CCIMX6 Module (U1.F10), 08 - Displays, HDMI, Cameras (J18.6)
DSI_CONTRAST: 02 - CCIMX6 Module (U1.Y10), 08 - Displays, HDMI, Cameras (J18.13)
DSI_D0_N: 02 - CCIMX6 Module (U1.C10), 08 - Displays, HDMI, Cameras (J18.4)
DSI_D0_P: 02 - CCIMX6 Module (U1.B10), 08 - Displays, HDMI, Cameras (J18.3)
DSI_D1_N: 02 - CCIMX6 Module (U1.E9), 08 - Displays, HDMI, Cameras (J18.10)
DSI_D1_P: 02 - CCIMX6 Module (U1.D9), 08 - Displays, HDMI, Cameras (J18.9)
DSI_I2C_SCL: 08 - Displays, HDMI, Cameras (J18.17), 10 - CAN, I2C, XBee (R101.2)
DSI_I2C_SDA: 08 - Displays, HDMI, Cameras (J18.18), 10 - CAN, I2C, XBee (R102.2)
DSI_IRQ_N: 02 - CCIMX6 Module (U1.U21), 08 - Displays, HDMI, Cameras (J18.12 R77.2)
DSI_PWR_EN: 02 - CCIMX6 Module (U1.AB12), 08 - Displays, HDMI, Cameras (J18.15)
DSI_RESET_N: 02 - CCIMX6 Module (U1.AD19), 08 - Displays, HDMI, Cameras (J18.14)
EXP_GPIO_0: 02 - CCIMX6 Module (U1.L24), 11 - Expansion Connectors, User LEDs (J30.6)
EXP_GPIO_1: 02 - CCIMX6 Module (U1.G22), 11 - Expansion Connectors, User LEDs (J30.7)
EXP_GPIO_2: 02 - CCIMX6 Module (U1.H23), 11 - Expansion Connectors, User LEDs (J30.8)
EXP_GPIO_3: 02 - CCIMX6 Module (U1.AC15), 11 - Expansion Connectors, User LEDs (J30.9)
EXP_GPIO_4: 02 - CCIMX6 Module (U1.Y14), 11 - Expansion Connectors, User LEDs (J30.10)
EXP_GPIO_5: 02 - CCIMX6 Module (U1.V16), 11 - Expansion Connectors, User LEDs (J30.11)
EXP_GPIO_6: 02 - CCIMX6 Module (U1.N2), 11 - Expansion Connectors, User LEDs (J30.12)
EXP_GPIO_7: 02 - CCIMX6 Module (U1.M2), 11 - Expansion Connectors, User LEDs (J30.13)
EXP_I2C_GPIO: 02 - CCIMX6 Module (U1.F23), 11 - Expansion Connectors, User LEDs (J28.5)
EXP_I2C_IRQ_N: 02 - CCIMX6 Module (U1.H24), 11 - Expansion Connectors, User LEDs (J28.4 R117.2)
EXP_I2C_SCL: 10 - CAN, I2C, XBee (R106.2), 11 - Expansion Connectors, User LEDs (J28.1)
EXP_I2C_SDA: 10 - CAN, I2C, XBee (R107.2), 11 - Expansion Connectors, User LEDs (J28.2)
HDMI_CEC_IN: 02 - CCIMX6 Module (U1.H2), 08 - Displays, HDMI, Cameras (R88.2 U16.16)
HDMI_CLK_N: 02 - CCIMX6 Module (U1.E8), 08 - Displays, HDMI, Cameras (P1.12 U16.15 U16.24)
HDMI_CLK_P: 02 - CCIMX6 Module (U1.F8), 08 - Displays, HDMI, Cameras (P1.10 U16.13 U16.26)
HDMI_D0_N: 02 - CCIMX6 Module (U1.A9), 08 - Displays, HDMI, Cameras (P1.9 U16.12 U16.27)
HDMI_D0_P: 02 - CCIMX6 Module (U1.B9), 08 - Displays, HDMI, Cameras (P1.7 U16.10 U16.29)
HDMI_D1_N: 02 - CCIMX6 Module (U1.B8), 08 - Displays, HDMI, Cameras (P1.6 U16.9 U16.30)
HDMI_D1_P: 02 - CCIMX6 Module (U1.C8), 08 - Displays, HDMI, Cameras (P1.4 U16.7 U16.32)
HDMI_D2_N: 02 - CCIMX6 Module (U1.F7), 08 - Displays, HDMI, Cameras (P1.3 U16.6 U16.33)
HDMI_D2_P: 02 - CCIMX6 Module (U1.G7), 08 - Displays, HDMI, Cameras (P1.1 U16.4 U16.35)
HDMI_HPD: 02 - CCIMX6 Module (U1.G9), 08 - Displays, HDMI, Cameras (C83.2 R90.2 U16.19)
HDMI_I2C_SCL: 08 - Displays, HDMI, Cameras (U16.17), 10 - CAN, I2C, XBee (R99.2)
HDMI_I2C_SDA: 08 - Displays, HDMI, Cameras (U16.18), 10 - CAN, I2C, XBee (R100.2)
I2C3_SCL: 02 - CCIMX6 Module (U1.T3), 10 - CAN, I2C, XBee (10 pins)
I2C3_SDA: 02 - CCIMX6 Module (U1.J3), 10 - CAN, I2C, XBee (10 pins)
JTAG_MOD: 02 - CCIMX6 Module (U1.G13), 05 - JTAG, SWD, Console, UART (R37.2)
JTAG_TCK: 02 - CCIMX6 Module (U1.F13), 05 - JTAG, SWD, Console, UART (J10.4)
JTAG_TDI: 02 - CCIMX6 Module (U1.D14), 05 - JTAG, SWD, Console, UART (J10.8)
JTAG_TDO: 02 - CCIMX6 Module (U1.E14), 05 - JTAG, SWD, Console, UART (J10.6)
JTAG_TMS: 02 - CCIMX6 Module (U1.F14), 05 - JTAG, SWD, Console, UART (J10.2)
JTAG_TRST_N: 02 - CCIMX6 Module (U1.D15), 05 - JTAG, SWD, Console, UART (R36.1)
LINE_IN_L: 09 - Audio (L21.1), 11 - Expansion Connectors, User LEDs (J26.4)
LINE_IN_R: 09 - Audio (L20.1), 11 - Expansion Connectors, User LEDs (J26.3)
LINE_OUT_L: 09 - Audio (L19.2), 11 - Expansion Connectors, User LEDs (J26.7)
LINE_OUT_R: 09 - Audio (L18.2), 11 - Expansion Connectors, User LEDs (J26.6)
LVDS0_CLK_N: 02 - CCIMX6 Module (U1.M4), 08 - Displays, HDMI, Cameras (J19.11)
LVDS0_CLK_P: 02 - CCIMX6 Module (U1.L4), 08 - Displays, HDMI, Cameras (J19.12)
LVDS0_CONTRAST: 02 - CCIMX6 Module (U1.V12), 08 - Displays, HDMI, Cameras (J19.16)
LVDS0_I2C_SCL: 08 - Displays, HDMI, Cameras (J19.17), 10 - CAN, I2C, XBee (R97.2)
LVDS0_I2C_SDA: 08 - Displays, HDMI, Cameras (J19.18), 10 - CAN, I2C, XBee (R98.2)
LVDS0_IRQ_N: 02 - CCIMX6 Module (U1.M3), 08 - Displays, HDMI, Cameras (J19.19 R76.2)
LVDS0_TX0_N: 02 - CCIMX6 Module (U1.J4), 08 - Displays, HDMI, Cameras (J19.2)
LVDS0_TX0_P: 02 - CCIMX6 Module (U1.H4), 08 - Displays, HDMI, Cameras (J19.3)
LVDS0_TX1_N: 02 - CCIMX6 Module (U1.F4), 08 - Displays, HDMI, Cameras (J19.5)
LVDS0_TX1_P: 02 - CCIMX6 Module (U1.E4), 08 - Displays, HDMI, Cameras (J19.6)
LVDS0_TX2_N: 02 - CCIMX6 Module (U1.C4), 08 - Displays, HDMI, Cameras (J19.8)
LVDS0_TX2_P: 02 - CCIMX6 Module (U1.B4), 08 - Displays, HDMI, Cameras (J19.9)
LVDS0_TX3_N: 02 - CCIMX6 Module (U1.R4), 08 - Displays, HDMI, Cameras (J19.14)
LVDS0_TX3_P: 02 - CCIMX6 Module (U1.P4), 08 - Displays, HDMI, Cameras (J19.15)
LVDS1_CLK_N: 02 - CCIMX6 Module (U1.E1), 11 - Expansion Connectors, User LEDs (J31.10)
LVDS1_CLK_P: 02 - CCIMX6 Module (U1.F1), 11 - Expansion Connectors, User LEDs (J31.9)
LVDS1_CONTRAST: 02 - CCIMX6 Module (U1.V13), 11 - Expansion Connectors, User LEDs (J31.13)
LVDS1_IRQ_N: 02 - CCIMX6 Module (U1.AC20), 11 - Expansion Connectors, User LEDs (J31.12 R118.2)
LVDS1_TX0_N: 02 - CCIMX6 Module (U1.H1), 11 - Expansion Connectors, User LEDs (J31.2)
LVDS1_TX0_P: 02 - CCIMX6 Module (U1.J1), 11 - Expansion Connectors, User LEDs (J31.1)
LVDS1_TX1_N: 02 - CCIMX6 Module (U1.M1), 11 - Expansion Connectors, User LEDs (J31.4)
LVDS1_TX1_P: 02 - CCIMX6 Module (U1.L1), 11 - Expansion Connectors, User LEDs (J31.3)
LVDS1_TX2_N: 02 - CCIMX6 Module (U1.P1), 11 - Expansion Connectors, User LEDs (J31.6)
LVDS1_TX2_P: 02 - CCIMX6 Module (U1.R1), 11 - Expansion Connectors, User LEDs (J31.5)
LVDS1_TX3_N: 02 - CCIMX6 Module (U1.U1), 11 - Expansion Connectors, User LEDs (J31.8)
LVDS1_TX3_P: 02 - CCIMX6 Module (U1.V1), 11 - Expansion Connectors, User LEDs (J31.7)
MCA_RESET_N: 02 - CCIMX6 Module (U1.N23), 05 - JTAG, SWD, Console, UART (J11.10)
MCA_SWD_CLK: 02 - CCIMX6 Module (U1.L23), 05 - JTAG, SWD, Console, UART (J11.4)
MCA_SWD_DIO: 02 - CCIMX6 Module (U1.M23), 05 - JTAG, SWD, Console, UART (J11.2)
MIC_BIAS: 09 - Audio (L23.1), 11 - Expansion Connectors, User LEDs (J26.1)
MIC_IN: 09 - Audio (L22.1), 11 - Expansion Connectors, User LEDs (J26.2)
ON/OFF: 02 - CCIMX6 Module (U1.D18), 03 - Power, Battery charger, boot (J3.1 SW1.3 SW1.4)
PCIE_DIS_N: 02 - CCIMX6 Module (U1.L3), 06 - Gigabit Ethernet, Mini PCIe, microSIM (J12.20)
PCIE_I2C_SCL: 06 - Gigabit Ethernet, Mini PCIe, microSIM (J12.30), 10 - CAN, I2C, XBee (R95.2)
PCIE_I2C_SDA: 06 - Gigabit Ethernet, Mini PCIe, microSIM (J12.32), 10 - CAN, I2C, XBee (R96.2)
PCIE_RESET_N: 02 - CCIMX6 Module (U1.D22), 06 - Gigabit Ethernet, Mini PCIe, microSIM (J12.22)
PCIE_RX_N: 02 - CCIMX6 Module (U1.A14), 06 - Gigabit Ethernet, Mini PCIe, microSIM (R44.1)
PCIE_RX_P: 02 - CCIMX6 Module (U1.B14), 06 - Gigabit Ethernet, Mini PCIe, microSIM (R47.1)
PCIE_TX_N: 02 - CCIMX6 Module (U1.A15), 06 - Gigabit Ethernet, Mini PCIe, microSIM (R51.1)
PCIE_TX_P: 02 - CCIMX6 Module (U1.B15), 06 - Gigabit Ethernet, Mini PCIe, microSIM (R52.1)
PCIE_WAKE_N: 02 - CCIMX6 Module (U1.F24), 06 - Gigabit Ethernet, Mini PCIe, microSIM (J12.1)
POR_N: 02 - CCIMX6 Module (U1.E18), 03 - Power, Battery charger, boot (5 pins), 05 - JTAG, SWD, Console, UART (J10.10)
PWR_EN: 02 - CCIMX6 Module (U1.AB9), 03 - Power, Battery charger, boot (R124.1)
PWR_OK: 02 - CCIMX6 Module (U1.AA23), 03 - Power, Battery charger, boot (R123.1)
RGMII_INT_N: 02 - CCIMX6 Module (U1.AA3), 06 - Gigabit Ethernet, Mini PCIe, microSIM (R40.1 U10.38)
RGMII_MDC: 02 - CCIMX6 Module (U1.W3), 06 - Gigabit Ethernet, Mini PCIe, microSIM (U10.36)
RGMII_MDIO: 02 - CCIMX6 Module (U1.Y3), 06 - Gigabit Ethernet, Mini PCIe, microSIM (R41.1 U10.37)
RGMII_RD0: 02 - CCIMX6 Module (U1.AA4), 06 - Gigabit Ethernet, Mini PCIe, microSIM (R60.1 U10.32)
RGMII_RD1: 02 - CCIMX6 Module (U1.AB3), 06 - Gigabit Ethernet, Mini PCIe, microSIM (R61.1 U10.31)
RGMII_RD2: 02 - CCIMX6 Module (U1.AC4), 06 - Gigabit Ethernet, Mini PCIe, microSIM (R62.1 U10.28)
RGMII_RD3: 02 - CCIMX6 Module (U1.AC5), 06 - Gigabit Ethernet, Mini PCIe, microSIM (R63.1 U10.27)
RGMII_REF_CLK: 02 - CCIMX6 Module (U1.Y1), 06 - Gigabit Ethernet, Mini PCIe, microSIM (R48.1)
RGMII_RESET_N: 02 - CCIMX6 Module (U1.P2), 06 - Gigabit Ethernet, Mini PCIe, microSIM (U10.42)
RGMII_RX_CTL: 02 - CCIMX6 Module (U1.V4), 06 - Gigabit Ethernet, Mini PCIe, microSIM (R58.1 R59.1 U10.33)
RGMII_RXC: 02 - CCIMX6 Module (U1.AD5), 06 - Gigabit Ethernet, Mini PCIe, microSIM (R57.1 U10.35)
RGMII_TD0: 02 - CCIMX6 Module (U1.U5), 06 - Gigabit Ethernet, Mini PCIe, microSIM (U10.19)
RGMII_TD1: 02 - CCIMX6 Module (U1.V5), 06 - Gigabit Ethernet, Mini PCIe, microSIM (U10.20)
RGMII_TD2: 02 - CCIMX6 Module (U1.Y5), 06 - Gigabit Ethernet, Mini PCIe, microSIM (U10.21)
RGMII_TD3: 02 - CCIMX6 Module (U1.AA5), 06 - Gigabit Ethernet, Mini PCIe, microSIM (U10.22)
RGMII_TX_CTL: 02 - CCIMX6 Module (U1.W4), 06 - Gigabit Ethernet, Mini PCIe, microSIM (U10.25)
RGMII_TXC: 02 - CCIMX6 Module (U1.U4), 06 - Gigabit Ethernet, Mini PCIe, microSIM (U10.24)
RS232_1_CTS_N: 05 - JTAG, SWD, Console, UART (U8.6), 11 - Expansion Connectors, User LEDs (J29.4)
RS232_1_RTS_N: 05 - JTAG, SWD, Console, UART (U8.11), 11 - Expansion Connectors, User LEDs (J29.3)
RS232_1_RX: 05 - JTAG, SWD, Console, UART (U8.5), 11 - Expansion Connectors, User LEDs (J29.2)
RS232_1_TX: 05 - JTAG, SWD, Console, UART (U8.10), 11 - Expansion Connectors, User LEDs (J29.1)
RS232_3_CTS_N: 05 - JTAG, SWD, Console, UART (U9.5), 11 - Expansion Connectors, User LEDs (J29.9)
RS232_3_RTS_N: 05 - JTAG, SWD, Console, UART (U9.10), 11 - Expansion Connectors, User LEDs (J29.8)
RS232_3_RX: 05 - JTAG, SWD, Console, UART (U9.4), 11 - Expansion Connectors, User LEDs (J29.7)
RS232_3_TX: 05 - JTAG, SWD, Console, UART (U9.9), 11 - Expansion Connectors, User LEDs (J29.6)
SATA_RX_N: 02 - CCIMX6 Module (U1.G19), 04 - SATA, microSD (C16.1)
SATA_RX_P: 02 - CCIMX6 Module (U1.H19), 04 - SATA, microSD (C17.1)
SATA_TX_N: 02 - CCIMX6 Module (U1.D19), 04 - SATA, microSD (C15.1)
SATA_TX_P: 02 - CCIMX6 Module (U1.E19), 04 - SATA, microSD (C14.1)
SD2_CLK: 02 - CCIMX6 Module (U1.K22), 04 - SATA, microSD (R35.1)
SD2_CMD: 02 - CCIMX6 Module (U1.M20), 04 - SATA, microSD (J7.3 R30.1)
SD2_DAT0: 02 - CCIMX6 Module (U1.P24), 04 - SATA, microSD (J7.7 R34.1)
SD2_DAT1: 02 - CCIMX6 Module (U1.K21), 04 - SATA, microSD (J7.8 R33.1)
SD2_DAT2: 02 - CCIMX6 Module (U1.R24), 04 - SATA, microSD (J7.1 R32.1)
SD2_DAT3: 02 - CCIMX6 Module (U1.K23), 04 - SATA, microSD (J7.2 R31.1)
SPI1_CLK: 02 - CCIMX6 Module (U1.AD20), 11 - Expansion Connectors, User LEDs (J34.1)
SPI1_MISO: 02 - CCIMX6 Module (U1.V17), 11 - Expansion Connectors, User LEDs (J34.2)
SPI1_MOSI: 02 - CCIMX6 Module (U1.AB18), 11 - Expansion Connectors, User LEDs (J34.3)
SPI1_SS0: 02 - CCIMX6 Module (U1.Y24), 11 - Expansion Connectors, User LEDs (J34.4)
SPI1_SS1/SPI1_IRQ_N: 02 - CCIMX6 Module (U1.K2), 11 - Expansion Connectors, User LEDs (J34.5 R122.2)
TOUCH_X1: 02 - CCIMX6 Module (U1.T23), 11 - Expansion Connectors, User LEDs (J30.1)
TOUCH_X2: 02 - CCIMX6 Module (U1.R23), 11 - Expansion Connectors, User LEDs (J30.2)
TOUCH_Y1: 02 - CCIMX6 Module (U1.U24), 11 - Expansion Connectors, User LEDs (J30.3)
TOUCH_Y2: 02 - CCIMX6 Module (U1.R22), 11 - Expansion Connectors, User LEDs (J30.4)
UART1_CTS_N: 02 - CCIMX6 Module (U1.Y17), 05 - JTAG, SWD, Console, UART (U8.12)
UART1_RTS_N: 02 - CCIMX6 Module (U1.W19), 05 - JTAG, SWD, Console, UART (U8.17)
UART1_RX: 02 - CCIMX6 Module (U1.E21), 05 - JTAG, SWD, Console, UART (U8.18)
UART1_TX: 02 - CCIMX6 Module (U1.C21), 05 - JTAG, SWD, Console, UART (U8.13)
UART3_CTS_N: 02 - CCIMX6 Module (U1.Y15), 05 - JTAG, SWD, Console, UART (U9.13)
UART3_RTS_N: 02 - CCIMX6 Module (U1.AA15), 05 - JTAG, SWD, Console, UART (U9.18)
UART3_RX: 02 - CCIMX6 Module (U1.AA17), 05 - JTAG, SWD, Console, UART (U9.19)
UART3_TX: 02 - CCIMX6 Module (U1.W20), 05 - JTAG, SWD, Console, UART (U9.14)
UART4_RX: 02 - CCIMX6 Module (U1.E2), 05 - JTAG, SWD, Console, UART (U8.19)
UART4_TX: 02 - CCIMX6 Module (U1.J2), 05 - JTAG, SWD, Console, UART (U8.14)
UART5_CTS_N: 02 - CCIMX6 Module (U1.D2), 10 - CAN, I2C, XBee (J24.5), 11 - Expansion Connectors, User LEDs (J29.14)
UART5_RTS_N: 02 - CCIMX6 Module (U1.L2), 10 - CAN, I2C, XBee (J24.9), 11 - Expansion Connectors, User LEDs (J29.13)
UART5_RX: 02 - CCIMX6 Module (U1.D3), 10 - CAN, I2C, XBee (J23.2), 11 - Expansion Connectors, User LEDs (J29.12)
UART5_TX: 02 - CCIMX6 Module (U1.E3), 10 - CAN, I2C, XBee (J23.3), 11 - Expansion Connectors, User LEDs (J29.11)
USB_HUB_RESET_N: 02 - CCIMX6 Module (U1.V21), 07 - USB OTG, USB HUB, USB Host (R69.2 U13.26)
USB_OTG_D_N: 02 - CCIMX6 Module (U1.G16), 07 - USB OTG, USB HUB, USB Host (L10.1)
USB_OTG_D_P: 02 - CCIMX6 Module (U1.G17), 07 - USB OTG, USB HUB, USB Host (L10.4)
USB_OTG_ID: 02 - CCIMX6 Module (U1.K3), 07 - USB OTG, USB HUB, USB Host (J16.4 U20.1)
USB_OTG_OC: 02 - CCIMX6 Module (U1.Y16), 07 - USB OTG, USB HUB, USB Host (R64.1 U12.2)
USB_OTG_PWR: 02 - CCIMX6 Module (U1.Y18), 07 - USB OTG, USB HUB, USB Host (U12.1)
USB_OTG_VBUS: 02 - CCIMX6 Module (U1.G14), 07 - USB OTG, USB HUB, USB Host (U15.D)
USBH3_D_N: 06 - Gigabit Ethernet, Mini PCIe, microSIM (J12.36), 07 - USB OTG, USB HUB, USB Host (L14.2)
USBH3_D_P: 06 - Gigabit Ethernet, Mini PCIe, microSIM (J12.38), 07 - USB OTG, USB HUB, USB Host (L14.3)
USBH4_D_N: 07 - USB OTG, USB HUB, USB Host (L16.2), 11 - Expansion Connectors, User LEDs (J32.3)
USBH4_D_P: 07 - USB OTG, USB HUB, USB Host (L16.3), 11 - Expansion Connectors, User LEDs (J32.2)
USBH4_OC_N: 07 - USB OTG, USB HUB, USB Host (U13.21), 11 - Expansion Connectors, User LEDs (J32.4)
USBH4_PWR_EN: 07 - USB OTG, USB HUB, USB Host (U13.20), 11 - Expansion Connectors, User LEDs (J32.5)
USBH_D_N: 02 - CCIMX6 Module (U1.C16), 07 - USB OTG, USB HUB, USB Host (U13.30)
USBH_D_P: 02 - CCIMX6 Module (U1.D16), 07 - USB OTG, USB HUB, USB Host (U13.31)
USER_LED0: 02 - CCIMX6 Module (U1.G21), 11 - Expansion Connectors, User LEDs (R121.2)
USER_LED1: 02 - CCIMX6 Module (U1.G23), 11 - Expansion Connectors, User LEDs (R120.2)
USER_LED2: 02 - CCIMX6 Module (U1.K24), 11 - Expansion Connectors, User LEDs (R119.2)
XBEE_ON/SLEEP_N: 02 - CCIMX6 Module (U1.AD18), 10 - CAN, I2C, XBee (J24.8)
XBEE_RESET_N: 02 - CCIMX6 Module (U1.AB17), 10 - CAN, I2C, XBee (J23.5)
XBEE_SLEEP_RQ: 02 - CCIMX6 Module (U1.W16), 10 - CAN, I2C, XBee (J23.9)

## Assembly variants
55001809-01: not fitted J11 R6 R20 R24 R25 R28 R29 R39 R53 R55 R59 R67 R79 R80 R123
